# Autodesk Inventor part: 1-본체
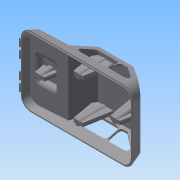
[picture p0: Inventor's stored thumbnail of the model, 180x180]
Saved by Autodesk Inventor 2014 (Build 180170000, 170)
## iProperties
Created: 2015-05
Part Number: 1-본체
Material: Generic
Document SubType Name: Modeling
Designer: Administrator
Density: 1 g/cm^3
Appearance: Default
Author: Administrator
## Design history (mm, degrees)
sketch "스케치1"
  geometry: L1 (0, 0)-(122, 0); L2 (122, 0)-(119.321, 10); L3 (119.321, 10)-(92, 30); L4 (42, 10.089)-(2.144, 8); L5 (2.144, 8)-(0, 0); L6 (92, 30)-(54.442, 30); L7 (54.442, 30)-(42, 10.089)
  constraints: 14 end point, 1 horizontal, 1 parallel
  dimensions: "d1" = 122 distance of L1.start L1.end; "d4" = 20 vertical distance of L3.end L2.end; "d5" = 30 horizontal distance of L3.end L1.end; "d7" = 8 vertical distance of L4.end L1.start; "d11" = 105 deg angle of L1 L5; "d53" = 30 horizontal distance of L3.end L1.end; "d59" = 105 deg angle of L1 L2; "d61" = 42 horizontal distance of L4.start L1.start; "d63" = 125 deg angle of L7 L4; "d64" = 3 deg angle of L1 L4
extrude "돌출1" new body sketch "스케치1" stored distance "d17" = 76; taper "d18" = 0 deg
sketch "스케치2"
  geometry: L1 (10, 38)-(30, 38) reference; L2 (0, 38)-(10, 38) reference; L3 (30, -38)-(10, -38) reference; L4 (10, -38)-(0, -38) reference; L5 (30, -38)-(30, 38) reference; L6 (0, -38)-(30, -29.962); L7 (0, 38)-(30, 38); L8 (30, -29.962)-(30, -38); L9 (0, -38)-(30, -38); L10 (0, 38)-(30, 29.962); L11 (30, 38)-(30, 29.962); 5 further points
  constraints: 12 end point, 2 collinear, 2 perpendicular, 2 point on line
  dimensions: "d20" = 15 deg angle of L3 L6; "d21" = 15 deg angle of L10 L1
extrude "돌출2" cut sketch "스케치2" stored distance "d22" = 76; taper "d23" = 0 deg
sketch "스케치3"
  geometry: L1 (11.441, 48.856)-(25.441, 48.856); L2 (28.441, 45.856)-(28.441, 25.856); L3 (25.441, 22.856)-(11.441, 22.856); L4 (8.441, 25.856)-(8.441, 45.856); L5 (-2.559, -2.144)-(-2.559, 73.856) reference; A1 r 3 centre (11.441, 45.856) between (11.441, 48.856) and (8.441, 45.856); A2 r 3 centre (11.441, 25.856) between (8.441, 25.856) and (11.441, 22.856); A3 r 3 centre (25.441, 25.856) between (25.441, 22.856) and (28.441, 25.856); A4 r 3 centre (25.441, 45.856) between (28.441, 45.856) and (25.441, 48.856); 5 further points
  constraints: 8 end point, 8 point on circle, 8 tangent, 6 point on line, 4 centre point, 3 equal radius, 2 midpoint, 2 parallel, 1 horizontal, 1 horizontal alignment, 1 perpendicular
  dimensions: "d24" = 20 distance of point (8.441, 48.856) point (28.441, 48.856); "d25" = 26 distance of point (8.441, 22.856) point (8.441, 48.856); "d27" = 3 radius of A1; "d51" = 11 distance from line of point (8.441, 35.856) L5
extrude "돌출3" join sketch "스케치3" distance "d28" = 5; taper "d29" = 0 deg
fillet "모깎기1" dims "d30" = 3
fillet "모깎기2" dims "d50" = 12
feature "쉘1" dims "d31" = 2
node "작업 평면1"
sketch "스케치5"
  geometry: A1 r 4 centre (0, 21) between (0, 25) and (0, 17); A2 r 4 centre (0, 10) between (0, 14) and (0, 6); A3 r 4 centre (0, -10) between (0, -6) and (0, -14); A4 r 4 centre (0, -21) between (0, -17) and (0, -25); 5 further points
  constraints: 8 point on circle, 4 centre point, 3 equal radius, 13 other
  dimensions: "d36" = 4 radius of A1; "d37" = 20 distance of A3.centre A2.centre; "d38" = 11 distance of A1.centre A2.centre; "d39" = 11 distance of A4.centre A3.centre; "d40" = 10 distance of point (0, 0) A2.centre
extrude "돌출5" join sketch "스케치5" stored distance "d41" = 1; taper "d42" = 0 deg
sketch "스케치6"
  geometry: L1 (56.332, 23.59)-(50.708, 14.59); L2 (53.253, 10)-(78.84, 10); L3 (81.84, 13)-(81.84, 22); L4 (78.84, 25)-(58.876, 25); L5 (82.856, 22)-(82.856, 13); L6 (85.856, 10)-(101.679, 10); L7 (103.451, 15.421)-(90.365, 25); L8 (90.365, 25)-(85.856, 25); L9 (42, 10.089)-(54.442, 30) reference; L10 (92, 30)-(104.901, 20.556) reference; L11 (54.442, 30)-(92, 30) reference; A1 r 3 centre (53.253, 13) between (50.708, 14.59) and (53.253, 10); A2 r 3 centre (58.876, 22) between (58.876, 25) and (56.332, 23.59); A3 r 3 centre (78.84, 22) between (81.84, 22) and (78.84, 25); A4 r 3 centre (78.84, 13) between (78.84, 10) and (81.84, 13); A5 r 3 centre (101.679, 13) between (101.679, 10) and (103.451, 15.421); A6 r 3 centre (85.856, 22) between (85.856, 25) and (82.856, 22); A7 r 3 centre (85.856, 13) between (82.856, 13) and (85.856, 10); 5 further points
  constraints: 16 end point, 14 point on circle, 14 tangent, 8 point on line, 7 centre point, 4 equal radius, 3 parallel, 2 collinear, 2 horizontal, 2 perpendicular, 1 vertical
  dimensions: "d43" = 34 distance of point (47.84, 10) point (81.84, 10); "d55" = 3 radius of A1; "d65" = 5 distance between parallel lines of L4 L11; "d66" = 5 distance between parallel lines of L10 L7; "d67" = 5 distance between parallel lines of L1 L9; "d68" = 3 radius of A6; "d69" = 15 distance between parallel lines of L2 L4; "d70" = 3 radius of A7; "d71" = 28 distance of point (110.856, 10) point (82.856, 10)
extrude "돌출6" cut sketch "스케치6" stored distance "d72" = 0; taper "d73" = 0 deg
sketch "스케치4"
  geometry: L1 (108.338, -11.73)-(108.338, -64.27) reference; L2 (98.679, -73.929)-(0.139, -73.929) reference; L3 (-9.521, -64.27)-(-9.521, -11.73) reference; L4 (0.139, -2.071)-(98.679, -2.071) reference; L5 (109.338, -11.73)-(109.338, -64.27); L6 (98.679, -74.929)-(0.139, -74.929); L7 (-10.521, -64.27)-(-10.521, -11.73); L8 (0.139, -1.071)-(98.679, -1.071); 4 further points; 4 other entities
  constraints: 8 end point, 7 parallel, 16 other
  dimensions: "d74" = 1 distance between parallel lines of L4 L8
extrude "돌출4" join sketch "스케치4" distance "d33" = 1; taper "d34" = 0 deg
sketch "스케치7"
  geometry: L1 (122, 0)-(110.409, 0) reference; L2 (11.591, 0)-(110.409, 0) reference; L3 (97, 0)-(92.169, 27.398); L4 (109.583, 14.65)-(107, 0); L5 (91.346, 28)-(105.555, 17.599) reference; L6 (105.555, 17.599)-(117.571, 8.802) reference; L7 (122, 0)-(119.321, 10) reference; L8 (102, 46.482)-(102, 0); L9 (92.169, 27.398)-(109.583, 14.65); L10 (97.73, 0)-(107, 0); L11 (27.392, 12.327)-(13.412, 11.595) reference; L12 (13.256, 11.574)-(15.297, 0); L13 (25.297, 0)-(27.472, 12.332); L14 (20.297, 0)-(20.297, 19.492); L15 (27.288, 14.325)-(13.307, 13.592) reference; L16 (27.392, 12.33)-(13.412, 11.595); A1 r 1 centre (13.464, 10.596) between (13.412, 11.595) and (12.471, 10.711) reference; A2 r 1 centre (27.445, 11.329) between (28.421, 11.547) and (27.392, 12.327) reference; A3 r 1 centre (13.464, 10.596) between (13.412, 11.595) and (13.257, 11.574); A4 r 1.003 centre (27.445, 11.329) between (27.472, 12.332) and (27.392, 12.33); 2 further points
  constraints: 18 end point, 11 point on line, 5 point on circle, 3 coincident, 3 perpendicular, 2 centre point, 1 collinear, 1 midpoint, 1 parallel, 1 tangent
  dimensions: "d94" = 20 distance from line of point (122, 0) L8; "d95" = 10 deg angle of L8 L3; "d97" = 10 deg angle of L4 L8; "d98" = 10 distance of L4.end L3.start; "d99" = 5 distance of L8.end L3.start; "d100" = 20 deg angle of L13 L12; "d101" = 10 distance of L13.start L12.end; "d102" = 5 distance from line of L13.start L14
extrude "돌출7" join sketch "스케치7" stored distance "d77" = 4; taper "d78" = 5 deg
sketch "스케치8"
  geometry: L1 (0, 0)-(10, 0) reference; L2 (-81.703, 0)-(-71.703, 0) reference; C1 r 3 at (5, 0); C2 r 3 at (-76.703, 0); 1 further point
  constraints: 2 centre point, 2 midpoint, 1 coincident, 1 equal radius
  dimensions: "d104" = 6 diameter of C2
extrude "돌출8" join sketch "스케치8" stored distance "d80" = 1; taper "d81" = 2 deg
sketch "스케치9"
  geometry: C1 r 3 at (50.409, -16); C2 r 3 at (50.409, -60); 2 further points
  constraints: 2 centre point, 1 equal radius, 1 vertical alignment
  dimensions: "d84" = 44 distance of C2.centre C1.centre; "d85" = 6 diameter of C1; "d86" = 22 vertical distance of point (-11.591, -38) C1.centre; "d107" = 40 horizontal distance of C1.centre point (90.409, -38)
extrude "돌출9" join sketch "스케치9" stored distance "d88" = 1; taper "d89" = 0 deg
extrude "돌출10" join sketch "스케치8" stored distance "d105" = 0; taper "d106" = 2 deg
node "작업 평면2"
sketch "스케치10"
  geometry: L1 (55.551, 28)-(91.346, 28) reference; L2 (43.144, 8.146)-(55.551, 28) reference; L3 (52.83, 23.647)-(57, 0); L4 (71.937, 28)-(67, 0); L5 (59, 0)-(59, 28) reference; L6 (65, 0)-(65, 28) reference; L7 (11.591, 0)-(110.409, 0) reference; 1 further point
  constraints: 4 end point, 4 point on line
  dimensions: "d109" = 20 deg angle of L4 L3; "d110" = 10 distance of L4.end L3.end; "d112" = 2 distance of L5.start L3.end; "d113" = 10 deg angle of L4 L6
extrude "돌출11" join sketch "스케치10" stored distance "d114" = 4; taper "d115" = 0 deg
sketch "스케치11"
  geometry: L1 (3.706, -38)-(13.706, -38) reference; L2 (85.409, -38)-(95.409, -38) reference; C1 r 3 at (50.409, -16); C2 r 3 at (8.706, -38); C3 r 3 at (50.409, -60); C4 r 3 at (90.409, -38); A1 r 3 centre (50.409, -16) between (48.173, -18) and (52.645, -18) reference; A2 r 3 centre (50.409, -16) between (52.645, -14) and (48.173, -14) reference; A3 r 3 centre (50.409, -60) between (52.645, -58) and (48.173, -58) reference; 9 further points; 2 other entities
  constraints: 4 centre point, 4 coincident, 3 equal radius, 2 midpoint, 2 other
  dimensions: "d116" = 6 diameter of C1
extrude "돌출12" join sketch "스케치11" stored distance "d117" = 4; taper "d118" = 0 deg
sketch "스케치12"
  geometry: L1 (-54.442, -35.962)-(-54.442, -23.962) reference; L2 (67.558, -3.553)-(67.558, -56.37) reference; 3 further points
  constraints: 1 horizontal alignment, 1 midpoint, 1 other
  dimensions: "d119" = 50 distance from line of L2 point (17.558, -29.962)
feature "엠보싱1" sketch "스케치12" dims "d7" = 8, "d21" = 15 deg, "d120" = 0.5, "d121" = 0
node "솔리드1"
mirror "대칭1"
other parameters: "d35" = -2, "d108" = 22
